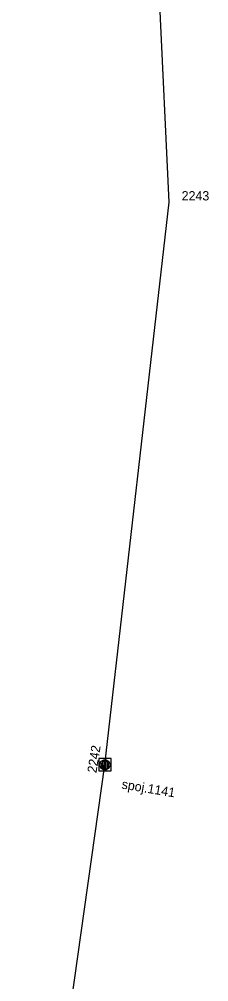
# Model space of a CAD drawing. Extents: x -535557 to -534097, y -1142175 to -1136716.
# Drawn here: x -534408.6 to -534393.3, y -1139559 to -1139481.4 of the extents above; entities that cross this region are included whole.
import ezdxf

# ---------------------------------------------------------------- set-up
doc = ezdxf.new("R2010")
doc.units = 0
doc.layers.add('Default', color=7, linetype='Continuous')
doc.layers.add('SS_SZDC', color=7, linetype='Continuous')

# ---------------------------------------------------------------- blocks, each defined once
blk = doc.blocks.new('POINT_DISPLAY')
at = {"layer": 'Default'}
blk.add_line((0, 0), (0, 0), dxfattribs=at)

msp = doc.modelspace()

# ---------------------------------------------------------------- linework, layer by layer
at = {"layer": 'SS_SZDC'}
for p, q in [((-534396.46, -1139496.149), (-534398.14, -1139461.36)), ((-534401.649, -1139541.54), (-534396.46, -1139496.149)), ((-534408.56, -1139590.44), (-534401.649, -1139541.54)), ((-534401.149, -1139541.04), (-534402.149, -1139541.04)), ((-534402.149, -1139541.04), (-534402.149, -1139542.04)), ((-534402.05, -1139541.636), (-534402.049, -1139541.436)), ((-534402.049, -1139541.436), (-534401.947, -1139541.237)), ((-534401.948, -1139541.387), (-534401.951, -1139541.687)), ((-534401.947, -1139541.237), (-534401.746, -1139541.139)), ((-534401.852, -1139541.838), (-534401.847, -1139541.288)), ((-534401.847, -1139541.288), (-534401.746, -1139541.189)), ((-534401.746, -1139541.189), (-534401.753, -1139541.889)), ((-534401.746, -1139541.139), (-534401.546, -1139541.14)), ((-534401.653, -1139541.889), (-534401.646, -1139541.19)), ((-534401.553, -1139541.89), (-534401.546, -1139541.19)), ((-534401.546, -1139541.14), (-534401.347, -1139541.242)), ((-534401.546, -1139541.19), (-534401.447, -1139541.291)), ((-534401.447, -1139541.291), (-534401.452, -1139541.841)), ((-534401.351, -1139541.692), (-534401.348, -1139541.392)), ((-534401.347, -1139541.242), (-534401.249, -1139541.443)), ((-534401.249, -1139541.443), (-534401.25, -1139541.643)), ((-534401.149, -1139542.04), (-534401.149, -1139541.04)), ((-534402.149, -1139542.04), (-534401.149, -1139542.04)), ((-534401.952, -1139541.837), (-534402.05, -1139541.636)), ((-534401.753, -1139541.939), (-534401.952, -1139541.837)), ((-534401.951, -1139541.687), (-534401.852, -1139541.838)), ((-534401.753, -1139541.889), (-534401.553, -1139541.89)), ((-534401.553, -1139541.94), (-534401.753, -1139541.939)), ((-534401.352, -1139541.842), (-534401.553, -1139541.94)), ((-534401.452, -1139541.841), (-534401.351, -1139541.692)), ((-534401.25, -1139541.643), (-534401.352, -1139541.842))]:
    msp.add_line(p, q, dxfattribs=at)

# ---------------------------------------------------------------- block references
for p in [(-534396.46, -1139496.149), (-534401.649, -1139541.54)]:
    msp.add_blockref('POINT_DISPLAY', p, dxfattribs=at)

# ---------------------------------------------------------------- texts
msp.add_text('2243', height=0.75, dxfattribs=at).set_placement((-534395.46, -1139495.999))
for s, rotation, p in [('2242', 81, (-534402.338, -1139542.237)), ('spoj.1141', 350.47566, (-534400.34, -1139543.452))]:
    msp.add_text(s, height=0.75, rotation=rotation, dxfattribs=at).set_placement(p)

doc.saveas('drawing.dxf')
